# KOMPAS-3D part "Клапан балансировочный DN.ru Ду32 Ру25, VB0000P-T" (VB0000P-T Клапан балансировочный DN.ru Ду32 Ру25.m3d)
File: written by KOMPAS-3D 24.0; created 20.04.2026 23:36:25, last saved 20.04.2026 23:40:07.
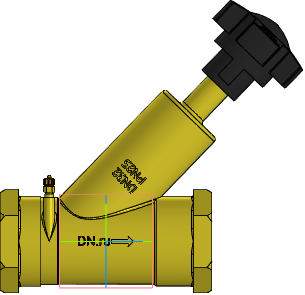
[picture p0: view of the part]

Document properties: Автор: DN.ru; Полное имя файла: E:\Работа\Зайцев\АУТСОРС\Диман\Балансировка\VB0000P-T Клапан балансировочный DN.ru Ду15-50 Ру25\DN32\VB0000P-T Клапан балансировочный DN.ru Ду32 Ру25.m3d

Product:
- Body: Тело 1  | qty 1
    Масса: 1.691588
- Part/product: Клапан балансировочный DN.ru Ду32 Ру25  | designation VB0000P-T
    Масса: 1
    Раздел спецификации: Прочие изделия
    Примечание: D080-01178

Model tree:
1. Операция без истории:1

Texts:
  VB0000P-T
